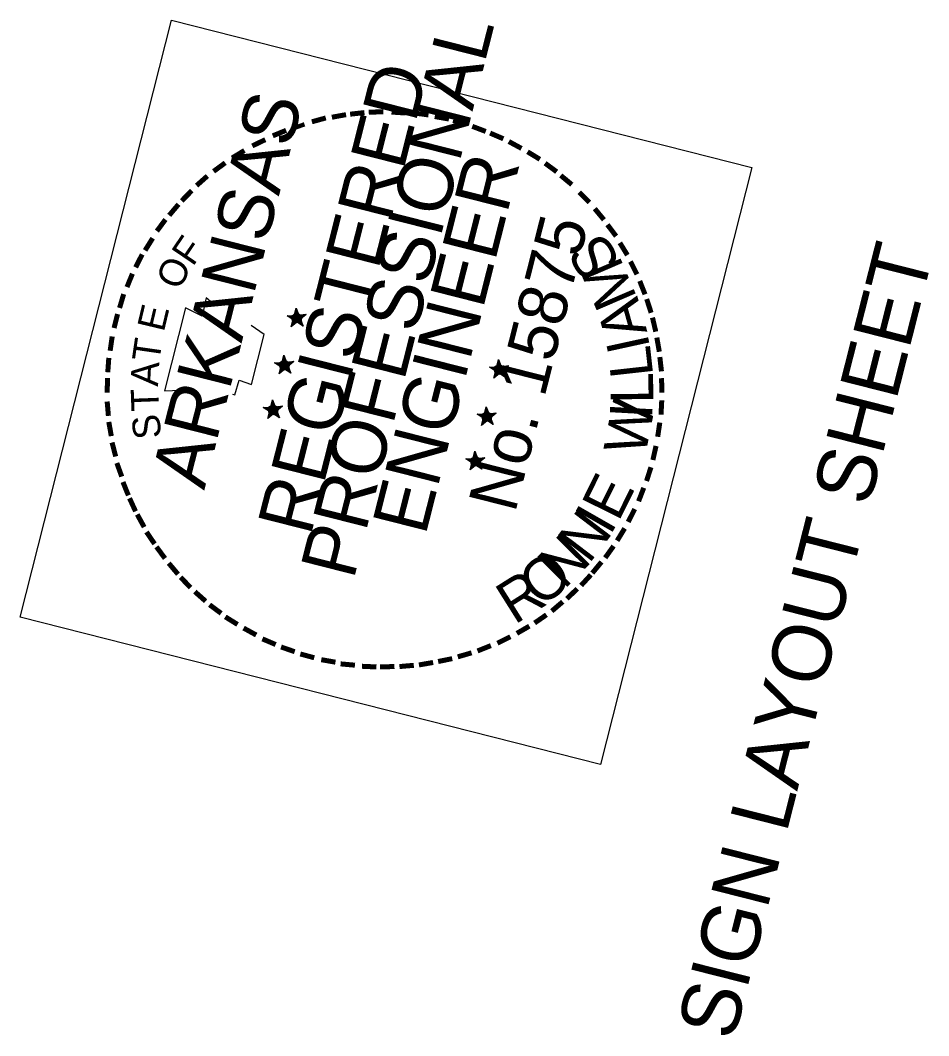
# Model space of a CAD drawing. Extents: x 670257 to 671518, y 737783 to 738188.
# Drawn here: x 671086.85 to 671095.08, y 737972.05 to 737981.25 of the extents above; entities that cross this region are included whole.
import ezdxf

# ---------------------------------------------------------------- set-up
doc = ezdxf.new("R2010")
doc.units = 0
for name, color, linetype in [('R_Border Notes', 7, 'Continuous'), ('R_Border PE', 7, 'Continuous'), ('R_Border Prem', 7, 'Continuous')]:
    doc.layers.add(name, color=color, linetype=linetype)

msp = doc.modelspace()

# ---------------------------------------------------------------- linework, layer by layer
at = {"layer": 'R_Border PE'}
for p, q in [((671089.3457, 737978.643), (671089.3315, 737978.5667)), ((671089.3457, 737978.643), (671089.34, 737978.5697)), ((671089.3457, 737978.643), (671089.3448, 737978.5684)), ((671089.3457, 737978.643), (671089.3508, 737978.5514)), ((671089.3457, 737978.643), (671089.3539, 737978.5842)), ((671089.3457, 737978.643), (671089.357, 737978.586)), ((671089.3457, 737978.643), (671089.3606, 737978.5902)), ((671089.2636, 737978.5736), (671089.3285, 737978.5752)), ((671089.3508, 737978.5514), (671089.2636, 737978.5736)), ((671089.2636, 737978.5736), (671089.3272, 737978.5703)), ((671089.2636, 737978.5736), (671089.323, 737978.5637)), ((671089.2636, 737978.5736), (671089.3229, 737978.5534)), ((671089.2636, 737978.5736), (671089.3217, 737978.5485)), ((671089.2636, 737978.5736), (671089.318, 737978.5443)), ((671089.3026, 737978.4734), (671089.3508, 737978.5514)), ((671089.3026, 737978.4734), (671089.3259, 737978.5346)), ((671089.3026, 737978.4734), (671089.3301, 737978.5309)), ((671089.3026, 737978.4734), (671089.3325, 737978.5303)), ((671089.3026, 737978.4734), (671089.3416, 737978.5254)), ((671089.3026, 737978.4734), (671089.3465, 737978.5242)), ((671089.3026, 737978.4734), (671089.3513, 737978.5229)), ((671089.41, 737978.4797), (671089.3495, 737978.526)), ((671089.4364, 737978.5839), (671089.3508, 737978.5514)), ((671089.41, 737978.4797), (671089.3508, 737978.5514)), ((671089.41, 737978.4797), (671089.3574, 737978.5266)), ((671089.4364, 737978.5839), (671089.3581, 737978.5702)), ((671089.4364, 737978.5839), (671089.3594, 737978.5751)), ((671089.41, 737978.4797), (671089.361, 737978.5308)), ((671089.4364, 737978.5839), (671089.3672, 737978.5653)), ((671089.4364, 737978.5839), (671089.3702, 737978.5465)), ((671089.41, 737978.4797), (671089.3702, 737978.5465)), ((671089.41, 737978.4797), (671089.3702, 737978.5362)), ((671089.4364, 737978.5839), (671089.3751, 737978.5556)), ((671089.4364, 737978.5839), (671089.3775, 737978.5447)), ((671089.41, 737978.4797), (671089.3781, 737978.5471)), ((671089.1499, 737978.1459), (671089.2172, 737978.1469)), ((671089.2396, 737978.1231), (671089.1499, 737978.1459)), ((671089.1499, 737978.1459), (671089.2136, 737978.1426)), ((671089.1499, 737978.1459), (671089.2117, 737978.1354)), ((671089.1499, 737978.1459), (671089.2093, 737978.1257)), ((671089.1499, 737978.1459), (671089.2105, 737978.1202)), ((671089.1499, 737978.1459), (671089.2074, 737978.1184)), ((671089.2345, 737978.2147), (671089.2202, 737978.1384)), ((671089.2345, 737978.2147), (671089.2287, 737978.1414)), ((671089.2345, 737978.2147), (671089.2336, 737978.1401)), ((671089.2345, 737978.2147), (671089.2396, 737978.1231)), ((671089.2345, 737978.2147), (671089.2427, 737978.1559)), ((671089.2345, 737978.2147), (671089.2464, 737978.1601)), ((671089.2345, 737978.2147), (671089.2494, 737978.1619)), ((671089.3258, 737978.158), (671089.2396, 737978.1231)), ((671089.3258, 737978.158), (671089.2457, 737978.1474)), ((671089.3258, 737978.158), (671089.2469, 737978.1419)), ((671089.3258, 737978.158), (671089.256, 737978.137)), ((671089.3258, 737978.158), (671089.259, 737978.1182)), ((671089.3258, 737978.158), (671089.2639, 737978.1273)), ((671089.3258, 737978.158), (671089.2663, 737978.1164)), ((671091.1795, 737978.1753), (671091.1659, 737978.1014)), ((671091.1795, 737978.1753), (671091.1744, 737978.1044)), ((671091.1795, 737978.1753), (671091.1792, 737978.1032)), ((671091.1795, 737978.1753), (671091.1852, 737978.0862)), ((671091.1795, 737978.1753), (671091.1878, 737978.1165)), ((671091.1795, 737978.1753), (671091.1938, 737978.1201)), ((671091.1795, 737978.1753), (671091.1969, 737978.1219)), ((671089.1914, 737978.0451), (671089.2396, 737978.1231)), ((671089.1914, 737978.0451), (671089.2123, 737978.1069)), ((671089.1914, 737978.0451), (671089.2171, 737978.1056)), ((671089.1914, 737978.0451), (671089.2213, 737978.102)), ((671089.1914, 737978.0451), (671089.2304, 737978.0971)), ((671089.1914, 737978.0451), (671089.2353, 737978.0959)), ((671089.1914, 737978.0451), (671089.2401, 737978.0946)), ((671089.2994, 737978.0538), (671089.2383, 737978.0977)), ((671089.2994, 737978.0538), (671089.2396, 737978.1231)), ((671089.2994, 737978.0538), (671089.2462, 737978.0983)), ((671089.2994, 737978.0538), (671089.2498, 737978.1025)), ((671089.2994, 737978.0538), (671089.2589, 737978.1079)), ((671089.2994, 737978.0538), (671089.259, 737978.1182)), ((671089.2994, 737978.0538), (671089.2669, 737978.1188)), ((671091.1852, 737978.0862), (671091.098, 737978.1083)), ((671091.098, 737978.1083), (671091.1623, 737978.1075)), ((671091.098, 737978.1083), (671091.1616, 737978.1051)), ((671091.098, 737978.1083), (671091.1598, 737978.0978)), ((671091.098, 737978.1083), (671091.1573, 737978.0881)), ((671091.098, 737978.1083), (671091.1561, 737978.0833)), ((671091.098, 737978.1083), (671091.1549, 737978.0784)), ((671091.1371, 737978.0081), (671091.1852, 737978.0862)), ((671091.1371, 737978.0081), (671091.1597, 737978.0669)), ((671091.1371, 737978.0081), (671091.1645, 737978.0656)), ((671091.1371, 737978.0081), (671091.1688, 737978.062)), ((671091.1371, 737978.0081), (671091.176, 737978.0602)), ((671091.1371, 737978.0081), (671091.1827, 737978.0559)), ((671091.1371, 737978.0081), (671091.1875, 737978.0547)), ((671091.2444, 737978.0144), (671091.1833, 737978.0583)), ((671091.2708, 737978.1186), (671091.1852, 737978.0862)), ((671091.2444, 737978.0144), (671091.1852, 737978.0862)), ((671091.2708, 737978.1186), (671091.1919, 737978.1025)), ((671091.2708, 737978.1186), (671091.1932, 737978.1074)), ((671091.2444, 737978.0144), (671091.1936, 737978.0583)), ((671091.2444, 737978.0144), (671091.1979, 737978.0649)), ((671091.2708, 737978.1186), (671091.2035, 737978.097)), ((671091.2444, 737978.0144), (671091.2046, 737978.071)), ((671091.2708, 737978.1186), (671091.2064, 737978.0782)), ((671091.2444, 737978.0144), (671091.2064, 737978.0782)), ((671091.2708, 737978.1186), (671091.2089, 737978.0879)), ((671091.2444, 737978.0144), (671091.2119, 737978.0794)), ((671091.2708, 737978.1186), (671091.2137, 737978.0764)), ((671089.1318, 737977.81), (671089.1176, 737977.7337)), ((671089.1318, 737977.81), (671089.1261, 737977.7367)), ((671089.1318, 737977.81), (671089.131, 737977.7354)), ((671089.1318, 737977.81), (671089.137, 737977.7185)), ((671089.1318, 737977.81), (671089.1401, 737977.7512)), ((671089.1318, 737977.81), (671089.1438, 737977.7554)), ((671089.1318, 737977.81), (671089.1468, 737977.7572)), ((671089.0473, 737977.7412), (671089.1146, 737977.7422)), ((671089.137, 737977.7185), (671089.0473, 737977.7412)), ((671089.0473, 737977.7412), (671089.111, 737977.7379)), ((671089.0473, 737977.7412), (671089.1097, 737977.7331)), ((671089.0473, 737977.7412), (671089.1073, 737977.7234)), ((671089.0473, 737977.7412), (671089.1078, 737977.7155)), ((671089.0473, 737977.7412), (671089.1048, 737977.7137)), ((671089.0888, 737977.6404), (671089.137, 737977.7185)), ((671089.0888, 737977.6404), (671089.1096, 737977.7022)), ((671089.0888, 737977.6404), (671089.1145, 737977.7009)), ((671089.0888, 737977.6404), (671089.1187, 737977.6973)), ((671089.0888, 737977.6404), (671089.1284, 737977.6948)), ((671089.0888, 737977.6404), (671089.1326, 737977.6912)), ((671089.0888, 737977.6404), (671089.1375, 737977.69)), ((671089.1968, 737977.6491), (671089.1357, 737977.693)), ((671089.2232, 737977.7533), (671089.137, 737977.7185)), ((671089.1968, 737977.6491), (671089.137, 737977.7185)), ((671089.2232, 737977.7533), (671089.1431, 737977.7427)), ((671089.1968, 737977.6491), (671089.1435, 737977.6936)), ((671089.2232, 737977.7533), (671089.1443, 737977.7372)), ((671089.1968, 737977.6491), (671089.1472, 737977.6978)), ((671089.2232, 737977.7533), (671089.1534, 737977.7323)), ((671089.2232, 737977.7533), (671089.1563, 737977.7135)), ((671089.1968, 737977.6491), (671089.1563, 737977.7135)), ((671089.1968, 737977.6491), (671089.1563, 737977.7032)), ((671089.2232, 737977.7533), (671089.1612, 737977.7226)), ((671089.2232, 737977.7533), (671089.1636, 737977.7117)), ((671089.1968, 737977.6491), (671089.1642, 737977.7141)), ((671091.074, 737977.6579), (671090.9868, 737977.68)), ((671090.9868, 737977.68), (671091.051, 737977.6792)), ((671090.9868, 737977.68), (671091.0504, 737977.6768)), ((671090.9868, 737977.68), (671091.0486, 737977.6695)), ((671090.9868, 737977.68), (671091.0461, 737977.6598)), ((671090.9868, 737977.68), (671091.0449, 737977.655)), ((671090.9868, 737977.68), (671091.0413, 737977.6507)), ((671091.0683, 737977.747), (671091.0547, 737977.6731)), ((671091.0683, 737977.747), (671091.0632, 737977.6761)), ((671091.0683, 737977.747), (671091.068, 737977.6749)), ((671091.0683, 737977.747), (671091.074, 737977.6579)), ((671091.0683, 737977.747), (671091.0765, 737977.6882)), ((671091.0683, 737977.747), (671091.0802, 737977.6924)), ((671091.0683, 737977.747), (671091.0863, 737977.696)), ((671091.1596, 737977.6903), (671091.074, 737977.6579)), ((671091.1596, 737977.6903), (671091.0807, 737977.6742)), ((671091.1596, 737977.6903), (671091.0826, 737977.6815)), ((671091.1596, 737977.6903), (671091.0904, 737977.6718)), ((671091.1596, 737977.6903), (671091.0958, 737977.6524)), ((671091.1596, 737977.6903), (671091.0977, 737977.6596)), ((671091.1596, 737977.6903), (671091.1001, 737977.6487)), ((671091.0259, 737977.5798), (671091.074, 737977.6579)), ((671091.0259, 737977.5798), (671091.0485, 737977.6386)), ((671091.0259, 737977.5798), (671091.0533, 737977.6373)), ((671091.0259, 737977.5798), (671091.0558, 737977.6367)), ((671091.0259, 737977.5798), (671091.0648, 737977.6318)), ((671091.0259, 737977.5798), (671091.0697, 737977.6306)), ((671091.0259, 737977.5798), (671091.0745, 737977.6294)), ((671091.1332, 737977.5861), (671091.0727, 737977.6324)), ((671091.1332, 737977.5861), (671091.074, 737977.6579)), ((671091.1332, 737977.5861), (671091.083, 737977.6324)), ((671091.1332, 737977.5861), (671091.0867, 737977.6366)), ((671091.1332, 737977.5861), (671091.0934, 737977.653)), ((671091.1332, 737977.5861), (671091.0934, 737977.6427)), ((671091.1332, 737977.5861), (671091.1007, 737977.6511)), ((671090.9662, 737977.3448), (671090.952, 737977.2684)), ((671090.9662, 737977.3448), (671090.9605, 737977.2714)), ((671090.9662, 737977.3448), (671090.9654, 737977.2702)), ((671090.9662, 737977.3448), (671090.9714, 737977.2532)), ((671090.9662, 737977.3448), (671090.9739, 737977.2835)), ((671090.9662, 737977.3448), (671090.9776, 737977.2877)), ((671090.9662, 737977.3448), (671090.9836, 737977.2914)), ((671090.8841, 737977.2753), (671090.949, 737977.2769)), ((671090.9714, 737977.2532), (671090.8841, 737977.2753)), ((671090.8841, 737977.2753), (671090.9478, 737977.2721)), ((671090.8841, 737977.2753), (671090.946, 737977.2648)), ((671090.8841, 737977.2753), (671090.9435, 737977.2551)), ((671090.8841, 737977.2753), (671090.9423, 737977.2503)), ((671090.8841, 737977.2753), (671090.9386, 737977.246)), ((671090.9232, 737977.1751), (671090.9714, 737977.2532)), ((671090.9232, 737977.1751), (671090.9465, 737977.2363)), ((671090.9232, 737977.1751), (671090.9507, 737977.2327)), ((671090.9232, 737977.1751), (671090.9531, 737977.232)), ((671090.9232, 737977.1751), (671090.9622, 737977.2272)), ((671090.9232, 737977.1751), (671090.967, 737977.2259)), ((671090.9232, 737977.1751), (671090.9719, 737977.2247)), ((671091.0306, 737977.1814), (671090.9701, 737977.2277)), ((671091.057, 737977.2856), (671090.9714, 737977.2532)), ((671091.0306, 737977.1814), (671090.9714, 737977.2532)), ((671091.057, 737977.2856), (671090.9781, 737977.2695)), ((671091.057, 737977.2856), (671090.9799, 737977.2768)), ((671091.0306, 737977.1814), (671090.9804, 737977.2277)), ((671091.0306, 737977.1814), (671090.984, 737977.2319)), ((671091.057, 737977.2856), (671090.9878, 737977.2671)), ((671091.0306, 737977.1814), (671090.9907, 737977.238)), ((671091.0306, 737977.1814), (671090.9908, 737977.2483)), ((671091.057, 737977.2856), (671090.9932, 737977.2477)), ((671091.057, 737977.2856), (671090.995, 737977.2549)), ((671091.057, 737977.2856), (671090.9974, 737977.244)), ((671091.0306, 737977.1814), (671090.998, 737977.2464))]:
    msp.add_line(p, q, dxfattribs=at)
for points in [[(671088.5903, 737978.685), (671088.5311, 737978.7361), (671088.4935, 737978.5677), (671088.3428, 737978.6446), (671088.1516, 737977.891)], [(671089.2636, 737978.5736), (671089.4364, 737978.5839), (671089.3026, 737978.4734), (671089.3457, 737978.643), (671089.41, 737978.4797), (671089.2636, 737978.5736)], [(671088.7682, 737977.861), (671088.79, 737977.8555), (671088.8293, 737977.9899), (671088.9401, 737977.9489), (671089.055, 737978.4021), (671088.9389, 737978.4831)], [(671089.1499, 737978.1459), (671089.3258, 737978.158), (671089.1914, 737978.0451), (671089.2345, 737978.2147), (671089.2994, 737978.0538), (671089.1499, 737978.1459)], [(671091.098, 737978.1083), (671091.2708, 737978.1186), (671091.1371, 737978.0081), (671091.1795, 737978.1753), (671091.2444, 737978.0144), (671091.098, 737978.1083)], [(671088.1516, 737977.891), (671088.3687, 737977.903)], [(671089.0473, 737977.7412), (671089.2232, 737977.7533), (671089.0888, 737977.6404), (671089.1318, 737977.81), (671089.1968, 737977.6491), (671089.0473, 737977.7412)], [(671090.9868, 737977.68), (671091.1596, 737977.6903), (671091.0259, 737977.5798), (671091.0683, 737977.747), (671091.1332, 737977.5861), (671090.9868, 737977.68)], [(671090.8841, 737977.2753), (671091.057, 737977.2856), (671090.9232, 737977.1751), (671090.9662, 737977.3448), (671091.0306, 737977.1814), (671090.8841, 737977.2753)]]:
    msp.add_lwpolyline(points, dxfattribs=at)
for centre, radius in [((671089.3514, 737978.5511), 0.0431), ((671089.3514, 737978.5511), 0.039), ((671089.3514, 737978.5511), 0.0361), ((671089.3514, 737978.5511), 0.0332), ((671089.3514, 737978.5511), 0.0289), ((671089.3514, 737978.5511), 0.0269), ((671089.3514, 737978.5511), 0.0248), ((671089.3514, 737978.5511), 0.0213), ((671089.3514, 737978.5511), 0.0187), ((671089.3514, 737978.5511), 0.0155), ((671089.3514, 737978.5511), 0.0124), ((671089.3514, 737978.5511), 0.00924), ((671089.3514, 737978.5511), 0.00741), ((671089.3514, 737978.5511), 0.0036), ((671089.2399, 737978.1236), 0.0431), ((671089.2399, 737978.1236), 0.039), ((671089.2399, 737978.1236), 0.0361), ((671089.2399, 737978.1236), 0.0332), ((671089.2399, 737978.1236), 0.0289), ((671089.2399, 737978.1236), 0.0269), ((671089.2399, 737978.1236), 0.0248), ((671089.2399, 737978.1236), 0.0213), ((671089.2399, 737978.1236), 0.0187), ((671089.2399, 737978.1236), 0.0155), ((671089.2399, 737978.1236), 0.0124), ((671089.2399, 737978.1236), 0.00924), ((671089.2399, 737978.1236), 0.00741), ((671089.2399, 737978.1236), 0.0036), ((671091.1863, 737978.0847), 0.0431), ((671091.1863, 737978.0847), 0.039), ((671091.1863, 737978.0847), 0.0361), ((671091.1863, 737978.0847), 0.0332), ((671091.1863, 737978.0847), 0.0289), ((671091.1863, 737978.0847), 0.0269), ((671091.1863, 737978.0847), 0.0248), ((671091.1863, 737978.0847), 0.0213), ((671091.1863, 737978.0847), 0.0187), ((671091.1863, 737978.0847), 0.0155), ((671091.1863, 737978.0847), 0.0124), ((671091.1863, 737978.0847), 0.00924), ((671091.1863, 737978.0847), 0.00741), ((671091.1863, 737978.0847), 0.0036), ((671089.1373, 737977.7191), 0.0431), ((671089.1373, 737977.7191), 0.039), ((671089.1373, 737977.7191), 0.0361), ((671089.1373, 737977.7191), 0.0332), ((671089.1373, 737977.7191), 0.0289), ((671089.1373, 737977.7191), 0.0269), ((671089.1373, 737977.7191), 0.0248), ((671089.1373, 737977.7191), 0.0213), ((671089.1373, 737977.7191), 0.0187), ((671089.1373, 737977.7191), 0.0155), ((671089.1373, 737977.7191), 0.0124), ((671089.1373, 737977.7191), 0.00924), ((671089.1373, 737977.7191), 0.00741), ((671089.1373, 737977.7191), 0.0036), ((671091.0748, 737977.6571), 0.0431), ((671091.0748, 737977.6571), 0.039), ((671091.0748, 737977.6571), 0.0361), ((671091.0748, 737977.6571), 0.0332), ((671091.0748, 737977.6571), 0.0289), ((671091.0748, 737977.6571), 0.0269), ((671091.0748, 737977.6571), 0.0248), ((671091.0748, 737977.6571), 0.0213), ((671091.0748, 737977.6571), 0.0187), ((671091.0748, 737977.6571), 0.0155), ((671091.0748, 737977.6571), 0.0124), ((671091.0748, 737977.6571), 0.00924), ((671091.0748, 737977.6571), 0.00741), ((671091.0748, 737977.6571), 0.0036), ((671090.9722, 737977.2527), 0.0431), ((671090.9722, 737977.2527), 0.039), ((671090.9722, 737977.2527), 0.0361), ((671090.9722, 737977.2527), 0.0332), ((671090.9722, 737977.2527), 0.0289), ((671090.9722, 737977.2527), 0.0269), ((671090.9722, 737977.2527), 0.0248), ((671090.9722, 737977.2527), 0.0213), ((671090.9722, 737977.2527), 0.0187), ((671090.9722, 737977.2527), 0.0155), ((671090.9722, 737977.2527), 0.0124), ((671090.9722, 737977.2527), 0.00924), ((671090.9722, 737977.2527), 0.00741), ((671090.9722, 737977.2527), 0.0036)]:
    msp.add_circle(centre, radius, dxfattribs=at)
at = {"layer": 'R_Border Prem'}
msp.add_lwpolyline([(671086.8459, 737975.8413), (671088.2176, 737981.2501), (671093.476, 737979.9164), (671092.1042, 737974.5077)], close=True, dxfattribs=at)

# ---------------------------------------------------------------- texts
at = {"layer": 'R_Border Notes'}
msp.add_text('SIGN LAYOUT SHEET', height=0.533593, rotation=75.76855, dxfattribs=at).set_placement((671093.3126, 737971.9918))
at = {"layer": 'R_Border PE'}
for s, height, rotation, p in [('PROFESSIONAL', 0.499995, 75.76855, (671089.8666, 737976.1716)), ('REGISTERED', 0.5, 75.76855, (671089.4768, 737976.5671)), ('ARKANSAS', 0.5, 75.76855, (671088.513, 737976.9869)), ('-', 0.3999, 6.34138, (671089.8289, 737980.2433)), ('-', 0.4, 0.89181, (671089.9836, 737980.2634)), ('-', 0.4, 356.31789, (671090.1776, 737980.2658)), ('-', 0.4, 352.36471, (671090.3723, 737980.2603)), ('-', 0.4, 15.4369, (671089.5073, 737980.1753)), ('-', 0.3999, 10.43135, (671089.6748, 737980.2154)), ('-', 0.4, 350.09866, (671090.5528, 737980.2299)), ('-', 0.3999, 345.70922, (671090.7073, 737980.1985)), ('-', 0.3999, 22.42073, (671089.1716, 737980.0515)), ('-', 0.35, 19.44384, (671089.3398, 737980.1352)), ('-', 0.3999, 339.28575, (671090.8661, 737980.1531)), ('-', 0.4, 336.76384, (671091.0217, 737980.0956)), ('-', 0.3999, 25.64828, (671088.9942, 737979.9624)), ('-', 0.3999, 331.53115, (671091.1797, 737980.0271)), ('-', 0.4, 31.34714, (671088.8259, 737979.8581)), ('-', 0.4, 328.63664, (671091.3431, 737979.9392)), ('-', 0.4, 36.29826, (671088.6703, 737979.7428)), ('ENGINEER', 0.5, 75.76855, (671090.5173, 737976.5714)), ('-', 0.4, 323.65722, (671091.492, 737979.8448)), ('-', 0.3999, 41.63121, (671088.5286, 737979.6214)), ('-', 0.4, 320.38827, (671091.628, 737979.7406)), ('-', 0.3999, 45.40945, (671088.402, 737979.4884)), ('-', 0.4, 314.8398, (671091.7858, 737979.6)), ('-', 0.4, 49.88964, (671088.2985, 737979.3651)), ('-', 0.4, 309.61379, (671091.9187, 737979.4631)), ('-', 0.4, 53.62364, (671088.1944, 737979.229)), ('No. 15875', 0.44, 75.76855, (671091.3304, 737976.7774)), ('-', 0.4, 307.02232, (671092.0304, 737979.3239)), ('-', 0.4, 58.10475, (671088.0956, 737979.0632)), ('F', 0.2499, 55.83921, (671088.4101, 737979.0118)), ('S', 0.3849, 121.46196, (671092.2995, 737979.0523)), ('-', 0.3999, 301.53388, (671092.1366, 737979.1732)), ('-', 0.4, 62.97344, (671088.0181, 737978.9204)), ('O', 0.2499, 66.22005, (671088.296, 737978.7958)), ('M', 0.3849, 113.32556, (671092.4404, 737978.7364)), ('-', 0.3999, 296.85364, (671092.2283, 737979.0158)), ('-', 0.4, 67.93028, (671087.9472, 737978.7527)), ('-', 0.3999, 291.50488, (671092.3084, 737978.8536)), ('-', 0.4, 73.51159, (671087.8872, 737978.577)), ('A', 0.3849, 105.76014, (671092.5301, 737978.4276)), ('-', 0.4, 288.01764, (671092.3697, 737978.6988)), ('-', 0.3999, 75.95478, (671087.8399, 737978.4008)), ('E', 0.25, 76.60089, (671088.1462, 737978.4185)), ('-', 0.4, 283.12539, (671092.4207, 737978.544)), ('-', 0.3999, 81.66537, (671087.8095, 737978.2099)), ('T', 0.25, 81.79131, (671088.1052, 737978.1452)), ('I', 0.3849, 102.33428, (671092.5571, 737978.2844)), ('-', 0.3999, 280.02017, (671092.4595, 737978.3717)), ('L', 0.3849, 96.33904, (671092.5837, 737978.0309)), ('-', 0.4, 85.9879, (671087.7913, 737978.0262)), ('A', 0.25, 86.98173, (671088.0942, 737977.9288)), ('-', 0.4, 276.48697, (671092.4868, 737978.2048)), ('L', 0.3849, 90.3438, (671092.5836, 737977.7759)), ('-', 0.3999, 89.3987, (671087.7883, 737977.8516)), ('-', 0.3999, 271.24284, (671092.5038, 737978.0277)), ('T', 0.2499, 92.17215, (671088.1037, 737977.7123)), ('-', 0.3999, 94.94463, (671087.8004, 737977.6551)), ('W', 0.3849, 78.78155, (671092.5086, 737977.2907)), ('-', 0.4, 267.05431, (671092.5074, 737977.8385)), ('S', 0.2499, 97.36257, (671088.1278, 737977.4715)), ('I', 0.3849, 86.91795, (671092.5717, 737977.6307)), ('-', 0.4, 100.07576, (671087.8271, 737977.4858)), ('-', 0.3999, 261.58522, (671092.4934, 737977.6512)), ('-', 0.4, 104.56037, (671087.8659, 737977.3135)), ('-', 0.4, 257.36031, (671092.463, 737977.45)), ('-', 0.4, 109.83212, (671087.9187, 737977.1454)), ('E', 0.3849, 63.72208, (671092.2683, 737976.6988)), ('-', 0.4, 252.28682, (671092.4224, 737977.2695)), ('-', 0.3999, 112.00029, (671087.9775, 737976.9808)), ('-', 0.4, 248.88401, (671092.3618, 737977.0914)), ('-', 0.3999, 114.71921, (671088.0407, 737976.8436)), ('I', 0.3849, 60.29623, (671092.1925, 737976.5743)), ('-', 0.3999, 118.7308, (671088.1155, 737976.7112)), ('N', 0.3849, 52.7308, (671091.9997, 737976.3169)), ('-', 0.4, 243.32407, (671092.2878, 737976.9116)), ('-', 0.4, 238.56682, (671092.2048, 737976.7469)), ('-', 0.4, 124.1916, (671088.2041, 737976.5726)), ('N', 0.3849, 45.16538, (671091.7747, 737976.0872)), ('-', 0.3999, 126.38273, (671088.2959, 737976.4462)), ('-', 0.4, 234.32977, (671092.1121, 737976.5951)), ('O', 0.3849, 38.88465, (671091.5662, 737975.9203)), ('-', 0.4, 130.00102, (671088.4088, 737976.3118)), ('-', 0.3999, 230.36875, (671092.0104, 737976.4584)), ('-', 0.4, 133.83918, (671088.517, 737976.1992)), ('R', 0.3849, 32.17569, (671091.3247, 737975.7684)), ('-', 0.3999, 227.33894, (671091.9203, 737976.3471)), ('-', 0.4, 223.85834, (671091.8046, 737976.2269)), ('-', 0.3999, 138.6399, (671088.6457, 737976.0866)), ('-', 0.3999, 143.54282, (671088.7776, 737975.9861)), ('-', 0.3999, 220.41489, (671091.6806, 737976.1139)), ('-', 0.3999, 148.16302, (671088.9167, 737975.8941)), ('-', 0.4, 214.70237, (671091.5468, 737976.0034)), ('-', 0.4, 151.22951, (671089.0795, 737975.8038)), ('-', 0.4, 209.99236, (671091.4034, 737975.9056)), ('-', 0.3999, 156.96982, (671089.243, 737975.7263)), ('-', 0.3999, 206.48667, (671091.2405, 737975.8128)), ('-', 0.3999, 160.95489, (671089.4059, 737975.6669)), ('-', 0.4, 201.662, (671091.0766, 737975.7358)), ('-', 0.4, 164.83079, (671089.5736, 737975.6166)), ('-', 0.3999, 169.96443, (671089.753, 737975.5814)), ('-', 0.3999, 191.4974, (671090.7536, 737975.6217)), ('-', 0.4, 196.21567, (671090.9163, 737975.6733)), ('-', 0.3999, 174.71648, (671089.9172, 737975.5578)), ('-', 0.4, 177.4835, (671090.1045, 737975.5438)), ('-', 0.4, 181.2264, (671090.258, 737975.5488)), ('-', 0.3999, 184.85597, (671090.4235, 737975.5609)), ('-', 0.3999, 189.83287, (671090.5849, 737975.5871))]:
    msp.add_text(s, height=height, rotation=rotation, dxfattribs=at).set_placement(p)

doc.saveas('drawing.dxf')
